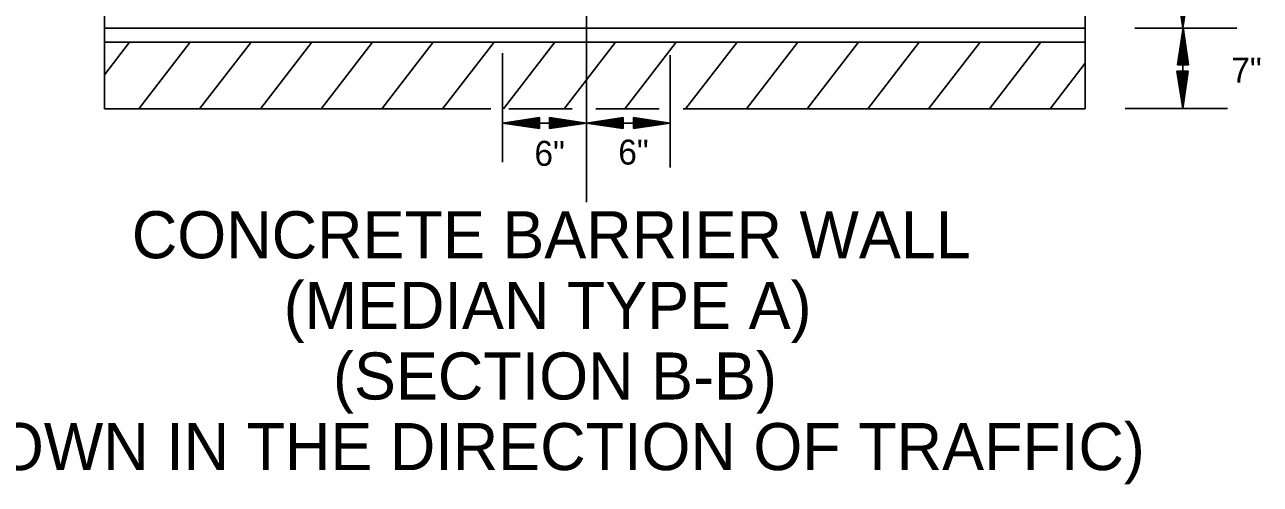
# Model space of a CAD drawing. Extents: x 714919 to 718439, y 1619644 to 1621844.
# Drawn here: x 715497 to 716010, y 1620910 to 1621101 of the extents above; entities that cross this region are included whole.
import ezdxf

# ---------------------------------------------------------------- set-up
doc = ezdxf.new("R2010")
doc.units = 0
for name, color, linetype in [('R_Annotation', 7, 'Continuous'), ('R_Centerline', 7, 'Continuous'), ('R_Dimension', 7, 'Continuous'), ('T_Drafting', 7, 'Continuous')]:
    doc.layers.add(name, color=color, linetype=linetype)

msp = doc.modelspace()

# ---------------------------------------------------------------- linework, layer by layer
at = {"layer": 'R_Centerline'}
for p, q in [((715730.36, 1621335.44), (715730.36, 1621073.04)), ((715730.36, 1621076.07), (715730.36, 1621066.48)), ((715730.36, 1621066.48), (715730.36, 1621026.99))]:
    msp.add_line(p, q, dxfattribs=at)
at = {"layer": 'R_Dimension'}
for p, q in [((715977.98, 1621099.22), (715977.98, 1621150.37)), ((715975.76, 1621114.6), (715978.01, 1621099.22)), ((715980.34, 1621114.6), (715978.01, 1621099.22)), ((716000.45, 1621099.22), (715958.02, 1621099.22)), ((715975.76, 1621083.92), (715978.1, 1621099.39)), ((715976.13, 1621084.02), (715978.12, 1621096.76)), ((715977.98, 1621065.84), (715977.98, 1621099.22)), ((715980.35, 1621083.95), (715978.1, 1621099.39)), ((715979.92, 1621083.92), (715978.12, 1621096.76)), ((715976.5, 1621084), (715978.15, 1621094.12)), ((715976.99, 1621083.97), (715978.11, 1621091.55)), ((715979.19, 1621083.96), (715978.11, 1621091.55)), ((715979.62, 1621084), (715978.15, 1621094.12)), ((715695.54, 1621088.85), (715695.54, 1621043.58)), ((715765.18, 1621087.99), (715765.18, 1621041.25)), ((715977.29, 1621084.01), (715978.08, 1621088.99)), ((715977.66, 1621083.99), (715978.05, 1621086.42)), ((715978.46, 1621084.01), (715978.05, 1621086.42)), ((715978.82, 1621083.98), (715978.08, 1621088.99)), ((715980.15, 1621081.33), (715975.56, 1621081.25)), ((715975.56, 1621081.25), (715977.98, 1621065.84)), ((715975.76, 1621083.92), (715980.35, 1621083.95)), ((715975.99, 1621081.29), (715977.93, 1621068.47)), ((715976.29, 1621081.22), (715977.87, 1621071.11)), ((715976.72, 1621081.26), (715977.88, 1621073.68)), ((715977.08, 1621081.24), (715977.88, 1621076.24)), ((715977.45, 1621081.22), (715977.89, 1621078.81)), ((715979.41, 1621081.25), (715977.87, 1621071.11)), ((715978.92, 1621081.27), (715977.88, 1621073.68)), ((715978.61, 1621081.23), (715977.88, 1621076.24)), ((715978.25, 1621081.24), (715977.89, 1621078.81)), ((715979.78, 1621081.23), (715977.93, 1621068.47)), ((715980.15, 1621081.33), (715977.98, 1621065.84)), ((715996.48, 1621065.84), (715954.06, 1621065.84)), ((715710.92, 1621062.07), (715695.54, 1621059.74)), ((715710.92, 1621062.07), (715695.54, 1621059.74)), ((715710.92, 1621061.72), (715698.13, 1621059.74)), ((715710.92, 1621061.72), (715698.13, 1621059.74)), ((715710.92, 1621061.29), (715700.81, 1621059.74)), ((715710.92, 1621061.29), (715700.81, 1621059.74)), ((715710.92, 1621060.95), (715703.32, 1621059.74)), ((715710.92, 1621060.95), (715703.32, 1621059.74)), ((715710.92, 1621057.49), (715710.92, 1621062.07)), ((715710.92, 1621057.49), (715710.92, 1621062.07)), ((715714.98, 1621062.07), (715730.36, 1621059.74)), ((715714.98, 1621062.07), (715714.98, 1621057.49)), ((715714.98, 1621062.07), (715730.36, 1621059.74)), ((715714.98, 1621062.07), (715714.98, 1621057.49)), ((715714.98, 1621061.72), (715727.77, 1621059.74)), ((715714.98, 1621061.72), (715727.77, 1621059.74)), ((715714.98, 1621061.29), (715725.09, 1621059.74)), ((715714.98, 1621061.29), (715725.09, 1621059.74)), ((715714.98, 1621060.95), (715722.58, 1621059.74)), ((715714.98, 1621060.95), (715722.58, 1621059.74)), ((715745.65, 1621062.07), (715730.36, 1621059.74)), ((715745.65, 1621061.72), (715732.86, 1621059.74)), ((715745.65, 1621061.29), (715735.54, 1621059.74)), ((715745.65, 1621060.95), (715738.05, 1621059.74)), ((715745.65, 1621057.49), (715745.65, 1621062.07)), ((715749.89, 1621062.07), (715765.18, 1621059.74)), ((715749.89, 1621062.07), (715749.89, 1621057.49)), ((715749.89, 1621062.07), (715765.18, 1621059.74)), ((715749.89, 1621062.07), (715749.89, 1621057.49)), ((715749.89, 1621061.72), (715762.67, 1621059.74)), ((715749.89, 1621061.72), (715762.67, 1621059.74)), ((715749.89, 1621061.29), (715759.99, 1621059.74)), ((715749.89, 1621061.29), (715759.99, 1621059.74)), ((715749.89, 1621060.95), (715757.49, 1621059.74)), ((715749.89, 1621060.95), (715757.49, 1621059.74)), ((715710.92, 1621057.49), (715695.54, 1621059.74)), ((715710.92, 1621057.49), (715695.54, 1621059.74)), ((715695.54, 1621059.74), (715761.29, 1621059.74)), ((715710.92, 1621057.84), (715698.13, 1621059.74)), ((715710.92, 1621057.84), (715698.13, 1621059.74)), ((715710.92, 1621058.27), (715700.81, 1621059.74)), ((715710.92, 1621058.27), (715700.81, 1621059.74)), ((715710.92, 1621058.61), (715703.32, 1621059.74)), ((715710.92, 1621058.61), (715703.32, 1621059.74)), ((715710.92, 1621060.51), (715705.91, 1621059.74)), ((715710.92, 1621060.51), (715705.91, 1621059.74)), ((715710.92, 1621059.05), (715705.91, 1621059.74)), ((715710.92, 1621059.05), (715705.91, 1621059.74)), ((715710.92, 1621060.17), (715708.41, 1621059.74)), ((715710.92, 1621060.17), (715708.41, 1621059.74)), ((715710.92, 1621059.39), (715708.41, 1621059.74)), ((715710.92, 1621059.39), (715708.41, 1621059.74)), ((715714.98, 1621060.51), (715719.99, 1621059.74)), ((715714.98, 1621060.51), (715719.99, 1621059.74)), ((715714.98, 1621060.17), (715717.49, 1621059.74)), ((715714.98, 1621060.17), (715717.49, 1621059.74)), ((715714.98, 1621057.49), (715730.36, 1621059.74)), ((715714.98, 1621059.05), (715719.99, 1621059.74)), ((715714.98, 1621058.27), (715725.09, 1621059.74)), ((715714.98, 1621057.84), (715727.77, 1621059.74)), ((715714.98, 1621058.61), (715722.58, 1621059.74)), ((715714.98, 1621059.39), (715717.49, 1621059.74)), ((715714.98, 1621057.49), (715730.36, 1621059.74)), ((715714.98, 1621059.05), (715719.99, 1621059.74)), ((715714.98, 1621058.27), (715725.09, 1621059.74)), ((715714.98, 1621057.84), (715727.77, 1621059.74)), ((715714.98, 1621058.61), (715722.58, 1621059.74)), ((715714.98, 1621059.39), (715717.49, 1621059.74)), ((715745.65, 1621057.49), (715730.36, 1621059.74)), ((715745.65, 1621057.84), (715732.86, 1621059.74)), ((715745.65, 1621058.27), (715735.54, 1621059.74)), ((715745.65, 1621058.61), (715738.05, 1621059.74)), ((715745.65, 1621060.51), (715740.64, 1621059.74)), ((715745.65, 1621059.05), (715740.64, 1621059.74)), ((715745.65, 1621060.17), (715743.23, 1621059.74)), ((715745.65, 1621059.39), (715743.23, 1621059.74)), ((715749.89, 1621060.51), (715754.9, 1621059.74)), ((715749.89, 1621060.51), (715754.9, 1621059.74)), ((715749.89, 1621060.17), (715752.3, 1621059.74)), ((715749.89, 1621060.17), (715752.3, 1621059.74)), ((715749.89, 1621057.49), (715765.18, 1621059.74)), ((715749.89, 1621059.05), (715754.9, 1621059.74)), ((715749.89, 1621058.27), (715759.99, 1621059.74)), ((715749.89, 1621057.84), (715762.67, 1621059.74)), ((715749.89, 1621058.61), (715757.49, 1621059.74)), ((715749.89, 1621059.39), (715752.3, 1621059.74)), ((715749.89, 1621057.49), (715765.18, 1621059.74)), ((715749.89, 1621059.05), (715754.9, 1621059.74)), ((715749.89, 1621058.27), (715759.99, 1621059.74)), ((715749.89, 1621057.84), (715762.67, 1621059.74)), ((715749.89, 1621058.61), (715757.49, 1621059.74)), ((715749.89, 1621059.39), (715752.3, 1621059.74))]:
    msp.add_line(p, q, dxfattribs=at)
at = {"layer": 'T_Drafting'}
for p, q in [((715530.22, 1621150.37), (715530.22, 1621065.62)), ((715937.5, 1621150.37), (715937.5, 1621065.62)), ((715937.5, 1621099.22), (715530.22, 1621099.22)), ((715937.5, 1621099.22), (715530.22, 1621099.22)), ((715937.5, 1621099.22), (715530.22, 1621099.22)), ((715530.22, 1621099.22), (715530.22, 1621093.36)), ((715937.5, 1621093.36), (715937.5, 1621099.22)), ((715540.62, 1621093.36), (715530.22, 1621093.36)), ((715530.22, 1621093.36), (715937.5, 1621093.36)), ((715530.22, 1621079.83), (715540.62, 1621093.36)), ((715544.52, 1621065.62), (715565.84, 1621093.36)), ((715569.74, 1621065.62), (715591.07, 1621093.36)), ((715594.97, 1621065.62), (715616.29, 1621093.36)), ((715620.2, 1621065.62), (715641.52, 1621093.36)), ((715645.42, 1621065.62), (715666.75, 1621093.36)), ((715670.65, 1621065.62), (715691.97, 1621093.36)), ((715695.87, 1621065.62), (715717.2, 1621093.36)), ((715721.1, 1621065.62), (715742.42, 1621093.36)), ((715746.32, 1621065.62), (715767.65, 1621093.36)), ((715771.55, 1621065.62), (715792.87, 1621093.36)), ((715796.78, 1621065.62), (715818.1, 1621093.36)), ((715822, 1621065.62), (715843.33, 1621093.36)), ((715847.23, 1621065.62), (715868.55, 1621093.36)), ((715872.45, 1621065.62), (715893.78, 1621093.36)), ((715897.68, 1621065.62), (715919, 1621093.36)), ((715922.9, 1621065.62), (715937.5, 1621084.61)), ((715690.61, 1621065.62), (715530.22, 1621065.62)), ((715724.37, 1621065.62), (715698.09, 1621065.62)), ((715760.49, 1621065.62), (715734.21, 1621065.62)), ((715937.5, 1621065.62), (715770.53, 1621065.62))]:
    msp.add_line(p, q, dxfattribs=at)

# ---------------------------------------------------------------- texts
at = {"layer": 'R_Annotation'}
for s, p in [('CONCRETE BARRIER WALL', (715541.58, 1621003.62)), ('(MEDIAN TYPE A)', (715604.65, 1620974.3)), ('(SECTION B-B)', (715625.11, 1620944.99)), ('(SHOWN IN THE DIRECTION OF TRAFFIC)', (715439.74, 1620915.67))]:
    msp.add_text(s, height=19.5366, dxfattribs=at).set_placement(p)
at = {"layer": 'R_Dimension'}
for s, p in [('7"', (715998.11, 1621076.57)), ('6"', (715708.76, 1621042.02)), ('6"', (715743.58, 1621042.54))]:
    msp.add_text(s, height=10.369, dxfattribs=at).set_placement(p)

doc.saveas('drawing.dxf')
